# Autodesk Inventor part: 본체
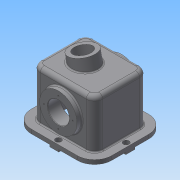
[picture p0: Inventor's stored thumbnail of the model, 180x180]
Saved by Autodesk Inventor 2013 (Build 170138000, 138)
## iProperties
Created: 2014-11
Part Number: 본체
Material: Generic
Document SubType Name: Modeling
Designer: Administrator
Density: 1 g/cm^3
Author: Administrator
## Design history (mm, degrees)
sketch "Sketch1"
  geometry: L1 (-76, 65)-(76, 65); L2 (76, 65)-(76, -65); L3 (76, -65)-(-76, -65); L4 (-76, -65)-(-76, 65); L5 (-76, 65)-(76, -65); L6 (76, 65)-(-76, -65); 1 further point
  constraints: 12 end point, 2 midpoint, 2 parallel, 1 horizontal, 1 perpendicular
  dimensions: "d0" = 152 distance of L2.end L3.end; "d1" = 130 distance of L1.end L2.end
extrude "Extrusion1" new body sketch "Sketch1" distance "d2" = 60; taper "d3" = 0 deg; dims "d88" = 58, "d89" = 0
fillet "Fillet1" dims "d4" = 20
fillet "Fillet2" dims "d5" = 10
shell "Shell1" dims "d6" = 10
sketch "Sketch2"
  geometry: L1 (-66, -45)-(-66, 45) reference; L2 (-56, 55)-(56, 55) reference; L3 (66, 45)-(66, -45) reference; L4 (56, -55)-(-56, -55) reference; L5 (56, 87)-(-56, 87); L6 (-98, 45)-(-98, -45); L7 (-56, -87)-(56, -87); L8 (98, -45)-(98, 45); L9 (98, 87)-(-98, -87); L10 (-98, 87)-(98, -87); A1 r 10 centre (-56, 45) between (-56, 55) and (-66, 45) reference; A2 r 10 centre (56, 45) between (66, 45) and (56, 55) reference; A3 r 10 centre (56, -45) between (56, -55) and (66, -45) reference; A4 r 10 centre (-56, -45) between (-66, -45) and (-56, -55) reference; A5 r 42 centre (56, 45) between (98, 45) and (56, 87); A6 r 42 centre (56, -45) between (56, -87) and (98, -45); A7 r 42 centre (-56, -45) between (-98, -45) and (-56, -87); A8 r 42 centre (-56, 45) between (-56, 87) and (-98, 45); 3 further points
  constraints: 12 end point, 8 point on circle, 8 point on line, 8 tangent, 4 centre point, 3 equal radius, 3 midpoint, 2 parallel, 1 horizontal, 1 horizontal alignment, 1 perpendicular
  dimensions: "d7" = 196 distance of L9.end L10.end; "d9" = 174 distance of L10.start L9.end; "d10" = 42 radius of A5; "d11" = 10 distance from line of point (88, 0) L8
extrude "Extrusion2" join sketch "Sketch2" distance "d12" = 10; taper "d13" = 0 deg
hole "Hole1" sketch "Sketch2" diameter "d14" = 9; stored, may be unused: countersink angle "d18" = 90 deg, drill point angle "d20" = 118 deg; dims "d15" = 6, "d16" = 14, "d17" = 8.6, "d19" = 8
mirror "Mirror1"
workplane "Work Plane1"
sketch "Sketch3"
  geometry: C1 r 45.5 at (0, 0); 1 further point
  constraints: 1 centre point, 1 coincident
  dimensions: "d22" = 91 diameter of C1
extrude "Extrusion3" join sketch "Sketch3" stored distance "d23" = 10; taper "d24" = 0 deg
sketch "Sketch4"
  geometry: C1 r 45.5 at (0, 0) reference; 1 further point
  constraints: 1 vertical alignment
  dimensions: "d25" = 35 distance of C1.centre point (0, -35)
hole "Hole2" sketch "Sketch4" at (0, -35) diameter "d26" = 3.242; stored, may be unused: countersink angle "d30" = 90 deg, drill point angle "d32" = 118 deg; dims "d27" = 13, "d28" = 14, "d29" = 8.6, "d31" = 16
pattern_circular "Circular Pattern1" dims angle "d34" = 360 deg
sketch "Sketch5"
  geometry: L1 (-78, 11)-(-98, 11); L2 (-98, 11)-(-98, -11); L3 (-98, -11)-(-78, -11); L4 (-78, -11)-(-78, 11); L5 (-78, 11)-(-98, -11); L6 (-98, 11)-(-78, -11); L7 (98, 11)-(78, 11); L8 (78, 11)-(78, -11); L9 (78, -11)-(98, -11); L10 (98, -11)-(98, 11); L11 (98, 11)-(78, -11); L12 (78, 11)-(98, -11); C1 r 4.5 at (-88, 0) reference; C2 r 4.5 at (88, 0) reference; 1 further point
  constraints: 24 end point, 4 midpoint, 4 parallel, 2 horizontal, 2 perpendicular
  dimensions: "d36" = 20 distance of L3.end L2.end; "d37" = 22 distance of L2.end L1.end; "d38" = 20 distance of L9.end L8.end; "d39" = 22 distance of L8.end L7.end
extrude "Extrusion4" join sketch "Sketch5" distance "d40" = 5; taper "d41" = 0 deg
sketch "Sketch6"
  geometry: L1 (-56, -87)-(56, -87) reference; 2 further points
  constraints: 1 vertical alignment
  dimensions: "d42" = 10 distance from line of L1 point (0, -77)
hole "Hole3" sketch "Sketch6" at (0, -77) diameter "d43" = 9; stored, may be unused: countersink angle "d47" = 90 deg, drill point angle "d49" = 118 deg; dims "d44" = 13, "d45" = 14, "d46" = 8.6, "d48" = 16
sketch "Sketch7"
  geometry: L1 (11, -67)-(-11, -67); L2 (-11, -67)-(-11, -87); L3 (-11, -87)-(11, -87); L4 (11, -87)-(11, -67); L5 (11, -67)-(-11, -87); L6 (-11, -67)-(11, -87); C1 r 4.5 at (0, -77) reference; 1 further point
  constraints: 12 end point, 2 midpoint, 2 parallel, 1 horizontal, 1 perpendicular
  dimensions: "d50" = 22 distance of L3.end L2.end; "d51" = 20 distance of L2.end L1.end
extrude "Extrusion5" join sketch "Sketch7" distance "d52" = 5; taper "d53" = 0 deg
mirror "Mirror2"
workplane "Work Plane3"
  workplane "Work Plane2"
sketch "Sketch8"
  geometry: C1 r 31 at (0, 0); 1 further point
  constraints: 1 centre point, 1 coincident
  dimensions: "d56" = 62 diameter of C1
extrude "Extrusion6" join sketch "Sketch8" stored distance "d57" = 5; taper "d58" = 0 deg
hole "Hole4" diameter "d61" = 30; stored, may be unused: countersink angle "d65" = 90 deg, drill point angle "d67" = 118 deg; dims "d59" = 10, "d60" = 10, "d62" = 13, "d63" = 42, "d64" = 25, "d66" = 16
sketch "Sketch9"
  geometry: L1 (81.5, -66.6)-(84, -66.6) reference; L2 (84, -66.6)-(84, -58) reference; L3 (84, -58)-(87, -58) reference; L4 (87, -58)-(87, -73) reference; L5 (87, -73)-(81.5, -73) reference; L6 (81.5, -73)-(81.5, -66.6) reference; L7 (-84, -66.6)-(-81.5, -66.6) reference; L8 (-81.5, -66.6)-(-81.5, -73) reference; L9 (-81.5, -73)-(-87, -73) reference; L10 (-87, -73)-(-87, -58) reference; L11 (-87, -58)-(-84, -58) reference; L12 (-84, -58)-(-84, -66.6) reference; L13 (-65, -58)-(-65, 50) reference; L14 (-55, 60)-(-28.379, 60) reference; L15 (-25.037, 87.921)-(-10.337, 87.921) reference; L16 (-16.519, 62.363)-(-7.542, 62.363) reference; L17 (-10.814, 50)-(-55, 50) reference; L18 (-55, 50)-(-55, -68) reference; L19 (-55, -68)-(-67, -68) reference; L20 (-67, -68)-(-67, -73) reference; L21 (-67, -73)-(-72.5, -73) reference; L22 (-72.5, -73)-(-72.5, -66.6) reference; L23 (-72.5, -66.6)-(-70, -66.6) reference; L24 (-70, -66.6)-(-70, -58) reference; L25 (-70, -58)-(-65, -58) reference; L26 (65, 50)-(65, 45.5) reference; L27 (65, 45.5)-(77, 45.5) reference; L28 (77, 45.5)-(77, 36.621) reference; L29 (77, 36.621)-(61, 36.621) reference; L30 (61, 36.621)-(60.026, 35) reference; L31 (60.026, 35)-(61, 33.379) reference; L32 (61, 33.379)-(77, 33.379) reference; L33 (77, 33.379)-(77, -33.379) reference; L34 (77, -33.379)-(61, -33.379) reference; L35 (61, -33.379)-(60.026, -35) reference; L36 (60.026, -35)-(61, -36.621) reference; L37 (61, -36.621)-(77, -36.621) reference; L38 (77, -36.621)-(77, -45.5) reference; L39 (77, -45.5)-(65, -45.5) reference; L40 (65, -45.5)-(65, -58) reference; L41 (65, -58)-(70, -58) reference; L42 (70, -58)-(70, -66.6) reference; L43 (70, -66.6)-(72.5, -66.6) reference; L44 (72.5, -66.6)-(72.5, -73) reference; L45 (72.5, -73)-(67, -73) reference; L46 (67, -73)-(67, -68) reference; L47 (67, -68)-(55, -68) reference; L48 (55, -68)-(55, 50) reference; L49 (55, 50)-(10.814, 50) reference; L50 (7.542, 62.363)-(16.519, 62.363) reference; L51 (10.337, 87.921)-(25.037, 87.921) reference; L52 (28.379, 60)-(55, 60) reference; L53 (55, 0)-(55, 45.5); L54 (55, 45.5)-(45, 35.5); L55 (45, 35.5)-(45, 0); L56 (45, 0)-(55, 0); A1 r 10 centre (-55, 50) between (-55, 60) and (-65, 50) reference; A2 r 10 centre (55, 50) between (65, 50) and (55, 60) reference; 7 further points; 6 other entities
  constraints: 8 end point, 2 perpendicular, 1 horizontal alignment, 1 parallel, 1 vertical alignment, 6 other
  dimensions: "d68" = 91 diameter of L53.end L56; "d70" = 71 diameter of L54.end L56; "d71" = 10 distance between parallel lines of L55 L53
revolve "Revolution1" sketch "Sketch9" stored, may be unused: angle "d72" = 90 deg
sketch "Sketch10"
  geometry: C1 r 45.5 at (0, 0) reference; C2 r 26 at (0, 0)
  constraints: 1 centre point, 1 coincident
  dimensions: "d73" = 52 diameter of C2
extrude "Extrusion7" cut sketch "Sketch10" stored distance "d74" = 5; taper "d75" = 0 deg
mirror "Mirror3"
chamfer "Chamfer2" distance "d80" = 1; stored, may be unused: second distance "d81" = 2, angle "d82" = 45 deg
fillet "Fillet4" dims "d83" = 3
fillet "Fillet5" dims "d84" = 0.3
sketch "Sketch11"
  geometry: L1 (-118, 56)-(-118, 90) reference; 2 further points
  constraints: 1 horizontal alignment, 1 other
  dimensions: "d85" = 92 distance from line of L1 point (-26, 45)
emboss "Emboss1" sketch "Sketch11" dims "d0" = 152, "d1" = 130, "d86" = 1, "d87" = 0
body "Solid1"
node "Project Cut Edges1"
other parameters: "d21" = 77, "d54" = -12 deg, "d55" = 86
